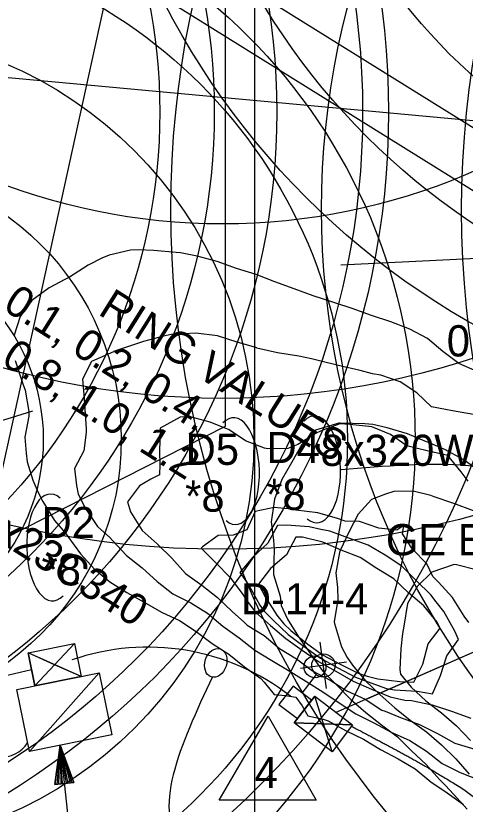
# Model space of a CAD drawing. Extents: x 1638506 to 1658005, y 834807 to 846788.
# Drawn here: x 1641459.3 to 1641632.2, y 842006.7 to 842309.7 of the extents above; entities that cross this region are included whole.
import ezdxf

# ---------------------------------------------------------------- set-up
doc = ezdxf.new("R2010")
doc.units = 0
for name, color, linetype in [('Default', 7, 'Continuous'), ('Old_Level_1', 7, 'Continuous'), ('Old_Level_2', 7, 'Continuous'), ('Old_Level_4', 7, 'Continuous'), ('Scratch_Level_0', 7, 'Continuous'), ('Sheet North Arrow CELL', 7, 'Continuous')]:
    doc.layers.add(name, color=color, linetype=linetype)

msp = doc.modelspace()

# ---------------------------------------------------------------- linework, layer by layer
at = {"layer": 'Default'}
for p, q in [((1641802.98, 842138.07), (1641390.68, 842394.71)), ((1641798.39, 842165.09), (1641501.67, 842349.79)), ((1641582.52, 842042.08), (1641701.01, 842093.9)), ((1641594.74, 842047.43), (1641692.03, 842089.98)), ((1641481.98, 842068.51), (1641466.63, 842052.18)), ((1641578.84, 842051.25), (1641576.46, 842068.96)), ((1641484.55, 842055.81), (1641464.05, 842064.88)), ((1641586.53, 842061.28), (1641568.8, 842058.91)), ((1641408.15, 842045), (1641465.34, 842058.53)), ((1641577.67, 842060.11), (1641577.67, 842060.11)), ((1641491.43, 842057.21), (1641496.25, 842033.41)), ((1641569.53, 842049.44), (1641574.96, 842056.55)), ((1641578.25, 842055.62), (1641578.25, 842055.62)), ((1641581, 842026.94), (1641574.32, 842048.33)), ((1641588.86, 842037.24), (1641566.46, 842038.03)), ((1641496.25, 842033.41), (1641464.57, 842026.99)), ((1641476.47, 842029.41), (1641490.79, 841895.46)), ((1641631.71, 842012.42), (1641796.51, 841888.28))]:
    msp.add_line(p, q, dxfattribs=at)
for points in [[(1641484.55, 842055.81), (1641466.63, 842052.18), (1641464.05, 842064.88), (1641481.98, 842068.51)], [(1641474.3, 842060.35), (1641481.98, 842068.51), (1641484.55, 842055.81)], [(1641474.3, 842060.35), (1641464.05, 842064.88), (1641466.63, 842052.18)], [(1641464.57, 842026.99), (1641459.75, 842050.79), (1641491.43, 842057.21)], [(1641567.69, 842039.64), (1641573.09, 842046.73), (1641565.98, 842052.15), (1641560.57, 842045.06)], [(1641581, 842026.94), (1641566.46, 842038.03), (1641574.32, 842048.33), (1641588.86, 842037.24)], [(1641577.66, 842037.64), (1641574.32, 842048.33), (1641566.46, 842038.03)], [(1641574.92, 842008.35), (1641537.53, 842008.35), (1641556.36, 842040.61)], [(1641577.66, 842037.64), (1641588.86, 842037.24), (1641581, 842026.94)]]:
    msp.add_lwpolyline(points, close=True, dxfattribs=at)
msp.add_lwpolyline([(1641478.04, 842014.69), (1641477.31, 842014.61), (1641476.47, 842029.41), (1641476.62, 842014.54), (1641475.89, 842014.46), (1641476.47, 842029.41), (1641475.15, 842014.38), (1641474.42, 842014.3), (1641476.47, 842029.41), (1641481.72, 842015.14), (1641480.99, 842015.01), (1641476.47, 842029.41), (1641480.25, 842014.98), (1641479.52, 842014.85), (1641476.47, 842029.41), (1641478.78, 842014.77), (1641474.42, 842014.3), (1641481.72, 842015.14), (1641476.47, 842029.41), (1641474.42, 842014.3)], dxfattribs=at)
msp.add_circle((1641577.65, 842060.09), 4.47, dxfattribs=at)
for centre, radius, start, end in [((1641510.17, 841978.09), 89.02, 51.9787, 109.175), ((1641454.05, 842036.7), 11.74, 201.7195, 327.0126)]:
    msp.add_arc(centre, radius, start, end, dxfattribs=at)
for centre, major_axis, start_param, end_param in [((1641543.47, 842134.74), (0.49, -20.52), 1.570796, 3.572354), ((1641574.66, 842135.42), (0.49, -20.52), 1.570796, 3.572354), ((1641543.47, 842134.74), (0.49, -20.52), 5.884886, 7.853982), ((1641574.66, 842135.42), (0.49, -20.52), 5.884886, 7.853982), ((1641473.1, 842105.4), (-0.49, 20.52), 5.884886, 7.853982), ((1641473.1, 842105.4), (-0.49, 20.52), 1.570796, 3.572354)]:
    msp.add_ellipse(centre, major_axis=major_axis, ratio=0.466223, start_param=start_param, end_param=end_param, dxfattribs=at)
msp.add_ellipse((1641536.26, 842061.06), major_axis=(-1.72, -5.4), ratio=0.730797, dxfattribs=at)
for points in [[(1641691.8, 842094.16), (1641672.44, 842122.11), (1641584.46, 842135.22)], [(1641534.97, 842055.74), (1641524.28, 841990.28), (1641544.84, 841979.79)], [(1641404.81, 841880.06), (1641436.37, 841894.52), (1641452.71, 842018.89)]]:
    msp.add_spline(points, degree=3, dxfattribs=at)
msp.add_open_spline([(1641588.47, 842036.73), (1641601.31, 842029.94), (1641617.02, 842021.43), (1641631.71, 842012.42)], degree=2, dxfattribs=at)
at = {"layer": 'Old_Level_1'}
for points in [[(1641637.66, 842134.7), (1641631.43, 842139.16), (1641624.65, 842142.91), (1641617.76, 842145.82), (1641617.34, 842145.98), (1641610.03, 842149.07), (1641602.14, 842151.41), (1641596.72, 842152.63), (1641593.62, 842152.95), (1641584.1, 842153.21), (1641583.59, 842153.22), (1641574.62, 842150.55), (1641569.31, 842144.99), (1641565.55, 842138.21), (1641561.66, 842131.54), (1641558.9, 842123.98), (1641558.28, 842120.37), (1641557.59, 842115.28), (1641558.48, 842108.25), (1641558.68, 842104.69), (1641558.51, 842095.9), (1641558.51, 842095.09), (1641560.98, 842086.67), (1641561.45, 842083.05), (1641563.79, 842077.87), (1641568.13, 842071.01), (1641572.67, 842064.5), (1641572.7, 842064.45), (1641577.34, 842057.97), (1641582.76, 842052.48), (1641588.2, 842047.03), (1641594.01, 842042.04), (1641599.99, 842037.28), (1641606.1, 842032.67), (1641611.6, 842027.28), (1641617.21, 842022.04), (1641622.36, 842016.21), (1641624.57, 842013.96), (1641627.73, 842010.67), (1641632.89, 842004.85)], [(1641635.4, 842119.45), (1641627.87, 842122.25), (1641620.25, 842124.93), (1641619.02, 842125.37), (1641612.21, 842127.08), (1641604.69, 842126.9), (1641601.55, 842125.9), (1641596.14, 842123.9), (1641591.03, 842118.18), (1641587.44, 842111.27), (1641584.05, 842104.2), (1641583.89, 842103.44), (1641582.49, 842095.7), (1641583.06, 842090), (1641583.23, 842085.39), (1641581.81, 842076.78), (1641581.95, 842076.21), (1641584.64, 842067.25), (1641586.86, 842063.08), (1641588.84, 842060.23), (1641593.8, 842054.15), (1641599.41, 842048.92), (1641605.09, 842043.75), (1641611.09, 842039.02), (1641617.29, 842034.52), (1641623.11, 842029.55), (1641628.59, 842024.13), (1641633.73, 842018.29)], [(1641636.94, 842096.66), (1641628.87, 842098.76), (1641627.9, 842098.93), (1641619.3, 842095.96), (1641613.84, 842090.52), (1641609.95, 842083.85), (1641608.6, 842075.18), (1641608.06, 842072.3), (1641607.38, 842066.41), (1641607.01, 842058.58), (1641607.28, 842056.75), (1641611.36, 842051.74), (1641616.99, 842046.52), (1641623.09, 842041.9), (1641628.84, 842036.83), (1641634.2, 842031.28)]]:
    msp.add_lwpolyline(points, dxfattribs=at)
for centre, radius in [((1641295.68, 842272.71), 365), ((1641995.81, 842234.97), 365), ((1641295.68, 842272.71), 307), ((1641295.68, 842272.71), 240)]:
    msp.add_circle(centre, radius, dxfattribs=at)
at = {"layer": 'Old_Level_2'}
for p, q in [((1641373.11, 842293.63), (1642246.71, 842213.27)), ((1641584.36, 842214), (1642127.44, 842240.91)), ((1641584.36, 842214), (1642127.44, 842240.91))]:
    msp.add_line(p, q, dxfattribs=at)
msp.add_arc((1641332.1, 842574.94), 438, 252.1948, 287.7872, dxfattribs=at)
at = {"layer": 'Old_Level_4'}
for centre, radius in [((1641538.84, 842469.72), 365), ((1641538.84, 842469.72), 307), ((1641538.84, 842469.72), 240), ((1641883.97, 842235.35), 365), ((1641883.97, 842235.35), 307), ((1641393.92, 842146.92), 219), ((1641393.92, 842146.92), 193), ((1641393.92, 842146.92), 157), ((1641393.92, 842146.92), 106), ((1641393.92, 842146.92), 76)]:
    msp.add_circle(centre, radius, dxfattribs=at)
at = {"layer": 'Scratch_Level_0'}
for points in [[(1641636.82, 842173.08), (1641629.7, 842176.12), (1641623.59, 842180.78), (1641617.65, 842185.7), (1641610.91, 842189.35), (1641603.57, 842192.06), (1641596.14, 842194.61), (1641588.72, 842197.19), (1641582.01, 842199.37), (1641581.23, 842199.64), (1641573.77, 842202.15), (1641566.39, 842204.79), (1641559.01, 842207.43), (1641551.79, 842210.31), (1641548.85, 842211.2), (1641544.21, 842212.63), (1641536.86, 842215.32), (1641529.07, 842217.3), (1641522.72, 842218.6), (1641520.98, 842218.8), (1641512.42, 842219.57), (1641506.41, 842219.83), (1641503.43, 842219.64), (1641495.26, 842217.8), (1641492.47, 842216.59), (1641487.14, 842213.88), (1641480.02, 842209.32), (1641478.24, 842208.34), (1641472.13, 842205.25), (1641465.5, 842200.38), (1641461.09, 842194.11), (1641458.63, 842186.63)], [(1641635.42, 842156.49), (1641627.26, 842157.88), (1641619.19, 842159.43), (1641613.54, 842164.81), (1641607.22, 842169.12), (1641599.78, 842171.68), (1641596.58, 842172.13), (1641591.82, 842173.38), (1641583.94, 842175.22), (1641576.13, 842177.17), (1641573.12, 842177.85), (1641568.19, 842178.92), (1641559.99, 842180.26), (1641552.09, 842182.06), (1641552.05, 842182.07), (1641544.5, 842184.36), (1641536.92, 842186.69), (1641528.61, 842187.78), (1641528.57, 842187.78), (1641519.16, 842187.19), (1641516.13, 842186.6), (1641508.46, 842184.54), (1641506.18, 842183.82), (1641496.98, 842180.66), (1641496.89, 842180.63), (1641488.52, 842176.86), (1641484.95, 842170.06), (1641485.68, 842162.7), (1641485.82, 842160.48), (1641486.47, 842151.03), (1641486.44, 842149.55), (1641485.58, 842142.55), (1641481.9, 842135.82), (1641482.72, 842129.27), (1641483.33, 842125.89), (1641486.17, 842120.39), (1641490.83, 842113.43), (1641495.48, 842109.2), (1641496.52, 842108.12), (1641501.89, 842102.29), (1641508.01, 842097.65), (1641513.71, 842092.34), (1641519.79, 842087.64), (1641526.66, 842084.2), (1641533.14, 842080.13), (1641539.03, 842075.13), (1641545.25, 842070.65), (1641551.34, 842065.95), (1641557.87, 842061.98), (1641564.46, 842058.07), (1641570.96, 842054.05), (1641577.4, 842049.93), (1641583.77, 842045.68), (1641590.19, 842041.51), (1641597.05, 842038.05), (1641603.78, 842034.38), (1641610.84, 842031.24), (1641617.31, 842027.16), (1641623.38, 842022.45), (1641630.25, 842019), (1641637.5, 842016.16)], [(1641459.06, 842177.31), (1641462.1, 842168.33), (1641462.9, 842165.86), (1641464.38, 842157.6), (1641464.36, 842155.9), (1641462.87, 842147.8), (1641463.37, 842141.61), (1641463.67, 842138.26), (1641465.89, 842131.25), (1641467.93, 842126.54), (1641469.8, 842123.1), (1641474.23, 842115.78), (1641478.49, 842110.85), (1641479.41, 842109.66), (1641484.25, 842102.99), (1641489.61, 842097.14), (1641495.57, 842092.25), (1641502.05, 842088.17), (1641508.74, 842084.44), (1641515.34, 842080.57), (1641522.35, 842077.34), (1641528.71, 842073.09), (1641534.89, 842068.55), (1641541.32, 842064.4), (1641547.28, 842059.52), (1641553.56, 842055.12), (1641554.94, 842053.71), (1641558.69, 842048.92), (1641563.1, 842048.58), (1641567.05, 842047.83), (1641569.43, 842044.6), (1641571.64, 842040.77), (1641577.59, 842039.46), (1641579.46, 842038.82), (1641586.13, 842035.07), (1641593.12, 842031.81), (1641599.64, 842027.81), (1641606.41, 842024.2), (1641612.99, 842020.3), (1641618.94, 842015.39), (1641625.28, 842011.1), (1641631.54, 842006.69)], [(1641633.29, 842130.95), (1641630.58, 842134.44), (1641625.49, 842140.71), (1641617.63, 842142.59), (1641613.32, 842143.52), (1641609.77, 842144.45), (1641603.51, 842148.86), (1641596.27, 842151.73), (1641587.85, 842152.71), (1641583.98, 842152.94), (1641577.41, 842150.49), (1641575.17, 842149.44), (1641567.83, 842145.02), (1641563.95, 842143.45), (1641556.24, 842143.28), (1641555, 842143.6), (1641547.73, 842146.4), (1641541.37, 842150.66), (1641534.17, 842153.58), (1641526.38, 842155.57), (1641522.54, 842155.44), (1641514.91, 842151.21), (1641514.66, 842142.33), (1641514.81, 842137.19), (1641514.68, 842133.28), (1641511.3, 842131.6), (1641506.93, 842129.12), (1641502.31, 842122.98), (1641503.44, 842119.11), (1641507.94, 842111.9), (1641513.77, 842106.81), (1641514.04, 842106.56), (1641519.34, 842101.29), (1641524.66, 842095.38), (1641530.93, 842090.97), (1641536.98, 842086.24), (1641542.62, 842080.82), (1641547.36, 842076.56), (1641548.32, 842075.53), (1641554.88, 842071.59), (1641560.79, 842066.62), (1641567.29, 842062.58), (1641573.48, 842058.05), (1641580.24, 842054.44), (1641586.69, 842050.32), (1641593.73, 842047.14), (1641600.12, 842042.94), (1641601.46, 842042.51), (1641607.36, 842040.08), (1641614.68, 842037.35), (1641621.57, 842033.94), (1641628.26, 842030.19), (1641635.88, 842027.95)], [(1641633.59, 842076.53), (1641631.86, 842079.01), (1641627.33, 842086.17), (1641621.98, 842092.04), (1641619.81, 842094.24), (1641617.38, 842099.08), (1641611.89, 842104.73), (1641608.13, 842110.63), (1641608.57, 842113.81), (1641605.88, 842112.04), (1641598.94, 842112.88), (1641591.48, 842115.38), (1641586.05, 842115.48), (1641583.13, 842116.49), (1641575.53, 842118.77), (1641567.11, 842119.76), (1641564.13, 842120.24), (1641558.7, 842120.75), (1641551.45, 842119.18), (1641548.26, 842112.15), (1641543.01, 842110.18), (1641537.19, 842110.07), (1641531.11, 842105.63), (1641530.69, 842105.13), (1641530.74, 842105.05), (1641536.33, 842099.56), (1641541.8, 842093.89), (1641546.73, 842087.36), (1641547.95, 842085.23), (1641551.51, 842080.6), (1641557.3, 842075.43), (1641563.17, 842070.4), (1641569.44, 842065.99), (1641575.71, 842061.6), (1641582.39, 842057.84), (1641589.07, 842054.1), (1641596.15, 842050.99), (1641603.31, 842048.01), (1641609.03, 842046.79), (1641611.48, 842046.62), (1641619.49, 842044.99), (1641626.98, 842042.52), (1641634.34, 842039.86)], [(1641629.62, 842069.99), (1641628.22, 842073.23), (1641623.94, 842080.78), (1641620.98, 842084.46), (1641618.98, 842087.27), (1641613.34, 842092.67), (1641607.77, 842098.18), (1641601.4, 842102.42), (1641594.82, 842106.33), (1641587.44, 842108.96), (1641580.13, 842111.71), (1641576.73, 842112.31), (1641572.14, 842113.38), (1641563.47, 842113.97), (1641559.95, 842113.83), (1641556.23, 842107.13), (1641550.58, 842101.65), (1641545.49, 842095.81), (1641548.98, 842090.94), (1641553.2, 842083.28), (1641555.04, 842080.76), (1641558.48, 842077.3), (1641564.13, 842071.93), (1641570.28, 842067.34), (1641576.51, 842062.87), (1641583.23, 842059.19), (1641590.03, 842055.63), (1641597.32, 842052.86), (1641601.93, 842051.26), (1641605, 842050.69), (1641613.73, 842050.19), (1641619.63, 842049.16), (1641622.69, 842056.27), (1641625.19, 842063.74), (1641629.62, 842069.99)], [(1641622.55, 842074.44), (1641621.4, 842076.75), (1641616.3, 842083), (1641610.41, 842088.02), (1641604.75, 842093.38), (1641598.17, 842097.29), (1641591.8, 842101.53), (1641584.51, 842104.32), (1641577.45, 842107.45), (1641569.6, 842109.34), (1641567.02, 842109.38), (1641563.51, 842102.55), (1641557.36, 842097.38), (1641552.71, 842091.27), (1641555.21, 842086.47), (1641559.78, 842079.37), (1641562.45, 842076.11), (1641565.1, 842073.46), (1641571.13, 842068.68), (1641577.31, 842064.15), (1641584.08, 842060.53), (1641591, 842057.16), (1641594.53, 842055.92), (1641598.63, 842054.93), (1641607, 842053.87), (1641612.42, 842053.7), (1641615.92, 842060.54), (1641617.91, 842068.32), (1641622.55, 842074.44)]]:
    msp.add_lwpolyline(points, dxfattribs=at)
for centre, radius in [((1641780.93, 842450.01), 297), ((1641780.93, 842450.01), 264), ((1641780.93, 842450.01), 219), ((1641780.93, 842450.01), 160), ((1641295.75, 842272.71), 297), ((1641295.75, 842272.71), 264), ((1641295.75, 842272.71), 219), ((1641574.41, 842059.54), 4.21)]:
    msp.add_circle(centre, radius, dxfattribs=at)
at = {"layer": 'Sheet North Arrow CELL'}
msp.add_line((1641551.29, 840916.24), (1641551.29, 842541.24), dxfattribs=at)
msp.add_lwpolyline([(1641540.04, 842526.99), (1641447.29, 842104.99), (1641540.04, 842151.99)], close=True, dxfattribs=at)

# ---------------------------------------------------------------- texts
at = {"layer": 'Default'}
for s, p in [('D5', (1641524.69, 842137.15)), ('D4', (1641555.76, 842137.83)), ('*8', (1641524.47, 842119.15)), ('*8', (1641555.65, 842119.83)), ('D2', (1641469.25, 842108.99)), ('*8', (1641469.25, 842090.99)), ('D-14-4', (1641545.91, 842079.68)), ('4', (1641551.18, 842012.95))]:
    msp.add_text(s, height=12, dxfattribs=at).set_placement(p)
at = {"layer": 'Scratch_Level_0'}
for s, p in [('0.1, 0.2, 0.4,', (1641453.92, 842197.02)), ('RING VALUES', (1641490.57, 842195.23)), ('0.8, 1.0, 1.2', (1641453.29, 842176.16)), ('GE ERL2x23C340', (1641393.41, 842144.81))]:
    msp.add_text(s, height=12, rotation=327.8202, dxfattribs=at).set_placement(p)
for s, p in [('0.1, 0.2, 0.4,', (1641625.1, 842178.82)), ('8x320W LED Fixtures', (1641576.57, 842136.74)), ('GE ERL2x23C340', (1641601.69, 842102.39))]:
    msp.add_text(s, height=12, dxfattribs=at).set_placement(p)

doc.saveas('drawing.dxf')
